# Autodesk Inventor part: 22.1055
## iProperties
Created: 2007-01
Part Number: 22.1055
Document SubType Name: Modeling
Designer: Andy Moles
Density: 1 g/cm^3
Mass: 3.97417 g
Surface Area: 32.835 cm^2
Volume: 3.97417 cm^3
Description: END CAP FOR HANDLE PROFILE LEFT GRAY
Vendor: S
Author: Andy Moles
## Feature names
1. Base1
